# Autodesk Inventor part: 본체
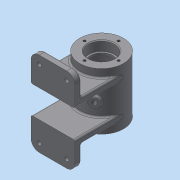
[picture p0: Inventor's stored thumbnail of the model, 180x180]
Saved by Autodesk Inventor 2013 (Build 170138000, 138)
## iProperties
Created: 2017-02
Part Number: 본체
Material: 일반
Document SubType Name: Modeling
Designer: dgall
Density: 1 g/cm^3
Author: dgall
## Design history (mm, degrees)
sketch "스케치1"
  geometry: C1 r 27 at (0, 0); 1 further point
  constraints: 1 centre point, 1 coincident
  dimensions: "d0" = 54 diameter of C1
extrude "돌출1" new body sketch "스케치1" stored distance "d2" = 70; taper "d3" = 0 deg
sketch "스케치2"
  geometry: L1 (0, 45.412)-(0, -44.194); L2 (0, 35)-(16, 35); L3 (16, 35)-(16, 23.3); L4 (15.7, 23)-(14, 23); L5 (14, 23)-(14, 20); L6 (14, 20)-(19, 20); L7 (22, 17)-(22, -17); L8 (19, -20)-(14, -20); L9 (14, -20)-(14, -23); L10 (14, -23)-(15.7, -23); L11 (16, -23.3)-(16, -35); L12 (16, -35)-(0, -35); L13 (27, 35)-(-27, 35) reference; L14 (-27, -35)-(27, -35) reference; L15 (0, -35)-(0, 35); A1 r 0.3 centre (15.7, 23.3) between (15.7, 23) and (16, 23.3); A2 r 0.3 centre (15.7, -23.3) between (16, -23.3) and (15.7, -23); A3 r 3 centre (19, -17) between (19, -20) and (22, -17); A4 r 3 centre (19, 17) between (22, 17) and (19, 20); 1 further point
  constraints: 26 end point, 8 point on circle, 8 tangent, 7 parallel, 4 centre point, 4 equal length, 3 perpendicular, 3 point on line, 2 collinear, 2 equal radius, 2 midpoint, 1 vertical
  dimensions: "d4" = 28 diameter of L5 L1; "d6" = 32 diameter of L3 L1; "d7" = 44 diameter of L7 L1; "d8" = 12 distance between parallel lines of L4 L2; "d9" = 40 distance between parallel lines of L6 L8; "d10" = 0.3 radius of A1; "d11" = 3 radius of A3
revolve "회전1" sketch "스케치2" stored, may be unused: angle "d12" = 90 deg
node "작업 평면1"
sketch "스케치3"
  geometry: L1 (27, -17)-(-27, -17); L2 (-27, -17)-(-27, -52); L3 (-27, -52)-(27, -52); L4 (27, -52)-(27, -17); L5 (0, 0)-(0, -39.11)
  constraints: 10 end point, 3 parallel, 1 horizontal, 1 perpendicular, 1 other
  dimensions: "d14" = 17 distance from line of L1 L5.start; "d15" = 52 distance from line of L3 L5.start; "d16" = 54 distance between parallel lines of L2 L4
extrude "돌출2" join sketch "스케치3" distance "d17" = 8; taper "d18" = 0 deg
sketch "스케치4"
  geometry: L1 (-27, -17)-(27, -17) reference; L2 (-27, -52)-(-27, -17) reference; L3 (27, -17)-(27, -52) reference; L4 (-27, -25)-(27, -25); 1 further point
  constraints: 2 end point, 2 point on line, 1 perpendicular
  dimensions: "d19" = 8 distance between parallel lines of L4 L1
extrude "돌출3" join sketch "스케치4" stored distance "d20" = 8; taper "d21" = 0 deg
fillet "모깎기1" dims "d22" = 10
fillet "모깎기2" dims "d23" = 2
fillet "모깎기3" dims "d24" = 2
fillet "모깎기4" dims "d25" = 2
fillet "모깎기5" dims "d26" = 2
hole "구멍1" diameter "d29" = 5; stored, may be unused: countersink angle "d33" = 90 deg, drill point angle "d35" = 118 deg; dims "d27" = 10, "d28" = 10, "d30" = 6, "d31" = 9, "d32" = 3, "d34" = 8
sketch "스케치5"
  geometry: L1 (-12.5, 39.402)-(-17, 36.804); L2 (-17, 36.804)-(-21.5, 39.402); L3 (-21.5, 39.402)-(-21.5, 44.598); L4 (-21.5, 44.598)-(-17, 47.196); L5 (-17, 47.196)-(-12.5, 44.598); L6 (-12.5, 44.598)-(-12.5, 39.402); A1 r 8 centre (-17, 42) between (-17, 50) and (-25, 42) reference; 4 further points
  constraints: 12 end point, 1 coincident, 1 horizontal alignment, 1 midpoint, 1 vertical alignment, 14 other
extrude "돌출4" cut sketch "스케치5" distance "d36" = 3; taper "d37" = 0 deg
node "작업 평면3"
  node "작업 평면2"
sketch "스케치6"
  geometry: L1 (-27, -35)-(27, -35) reference; C1 r 5 at (0, -10); 1 further point
  constraints: 1 centre point, 1 vertical alignment
  dimensions: "d42" = 25 distance from line of C1.centre L1; "d43" = 10 diameter of C1
extrude "돌출5" join sketch "스케치6" stored distance "d44" = 3; taper "d45" = 0 deg
hole "구멍2" diameter "d48" = 5.188; stored, may be unused: countersink angle "d52" = 90 deg, drill point angle "d54" = 118 deg; dims "d46" = 10, "d47" = 10, "d49" = 10, "d50" = 9, "d51" = 3, "d53" = 8
sketch "스케치7"
  geometry: C1 r 16 at (0, 0) reference; 1 further point
  constraints: 1 vertical alignment
  dimensions: "d55" = 21 distance of point (0, 21) C1.centre
hole "구멍3" sketch "스케치7" at (0, 21) diameter "d56" = 3.242; stored, may be unused: countersink angle "d60" = 90 deg, drill point angle "d62" = 118 deg; dims "d57" = 8, "d58" = 9, "d59" = 3, "d61" = 10
sketch "스케치8"
  geometry: L1 (0, 0)-(16.339, -25.16); L2 (0, 0)-(0, -34.628)
  constraints: 4 end point, 2 point on line, 1 vertical
  dimensions: "d66" = 33 deg angle of L1 L2; "d67" = 30 distance of L1.end L1.start
node "작업 평면4"
sketch "스케치9"
  geometry: C1 r 6 at (0, 0); 1 further point
  constraints: 1 centre point, 1 coincident
  dimensions: "d68" = 12 diameter of C1
extrude "돌출6" join sketch "스케치9" stored distance "d70" = 3; taper "d71" = 0 deg
hole "구멍4" diameter "d74" = 5.188; stored, may be unused: countersink angle "d78" = 90 deg, drill point angle "d80" = 118 deg; dims "d72" = 10, "d73" = 10, "d75" = 8, "d76" = 9, "d77" = 3, "d79" = 10
node "작업 평면5"
sketch "스케치10"
  geometry: L1 (-27, -35)-(27, -35) reference; L2 (-27, -35)-(-27, 35) reference; 2 further points
  constraints: 1 other
  dimensions: "d81" = 35 distance from line of point (0, 0) L1; "d82" = 27 distance from line of point (0, 0) L2
feature "엠보싱1" sketch "스케치10" dims "d4" = 28, "d6" = 32, "d7" = 44, "d8" = 12, "d9" = 40, "d10" = 0.3, "d11" = 3, "d83" = 0.5, "d84" = 0
chamfer "모따기1" distance "d85" = 1; stored, may be unused: second distance "d86" = 2, angle "d87" = 45 deg
fillet "모깎기6" dims "d88" = 2
fillet "모깎기7" dims "d89" = 2
node "솔리드1"
pattern_linear "직사각형 패턴1" dims "d40" = 34
mirror "대칭1"
pattern_circular "원형 패턴1" dims angle "d64" = 360 deg
mirror "대칭2"
other parameters: "d41" = 5
